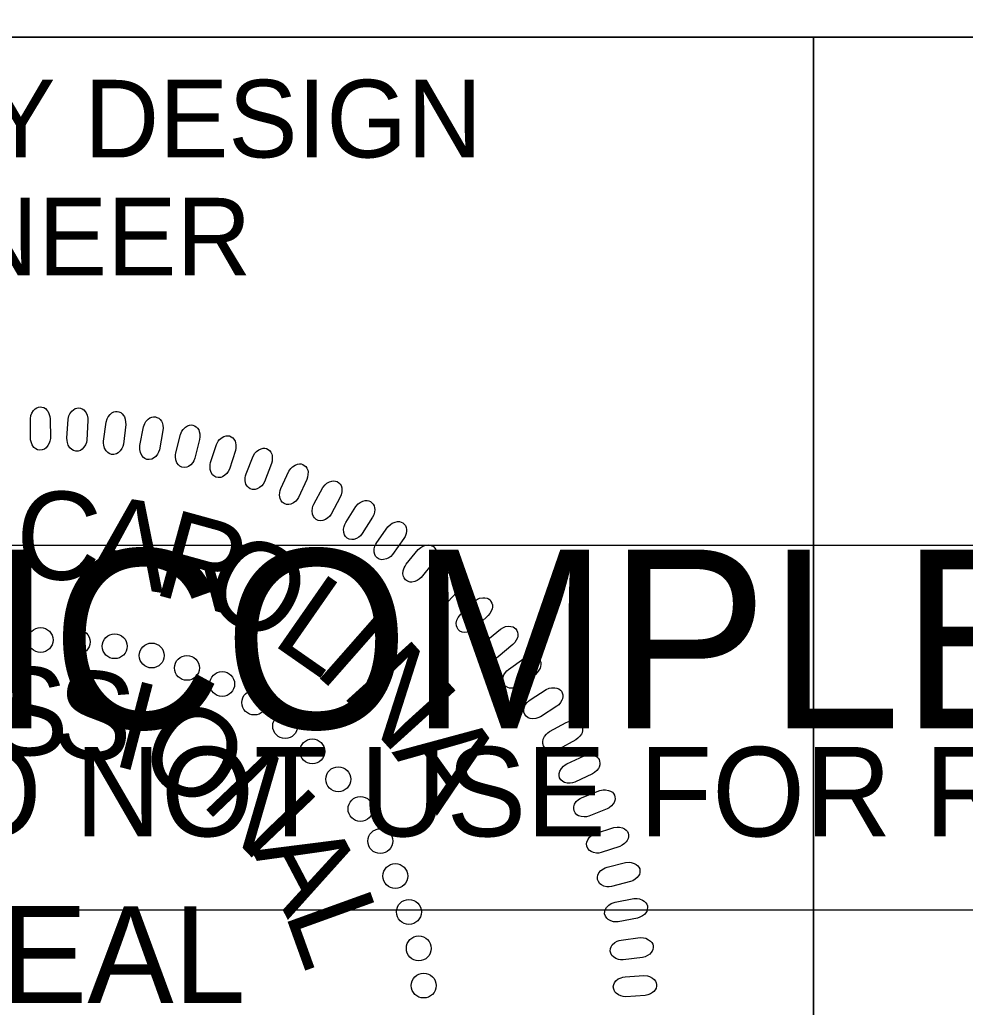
# Model space of a CAD drawing. Extents: x 505602 to 507286, y 483109 to 484209.
# Drawn here: x 507117.9 to 507178.9, y 484096.2 to 484159.8 of the extents above; entities that cross this region are included whole.
import ezdxf

# ---------------------------------------------------------------- set-up
doc = ezdxf.new("R2010")
doc.units = 0
for name, color, linetype in [('Sheet PE Seal Cell', 7, 'Continuous'), ('Sheet Profile CELL', 7, 'Continuous'), ('Sheet Sticker Incomplete CELL', 7, 'Continuous')]:
    doc.layers.add(name, color=color, linetype=linetype)

msp = doc.modelspace()

# ---------------------------------------------------------------- linework, layer by layer
at = {"layer": 'Sheet PE Seal Cell'}
for points in [[(507118.615, 484132.849), (507118.615, 484134.076), (507118.653, 484134.295), (507118.705, 484134.435), (507118.817, 484134.605), (507118.915, 484134.714), (507119.027, 484134.794), (507119.131, 484134.834), (507119.244, 484134.854), (507119.355, 484134.834), (507119.475, 484134.804), (507119.58, 484134.744), (507119.684, 484134.644), (507119.744, 484134.564), (507119.811, 484134.415), (507119.871, 484134.235), (507119.894, 484134.075), (507119.901, 484132.819), (507119.878, 484132.649), (507119.833, 484132.51), (507119.744, 484132.351), (507119.631, 484132.21), (507119.534, 484132.131), (507119.377, 484132.071), (507119.228, 484132.052), (507119.078, 484132.091), (507118.974, 484132.141), (507118.846, 484132.241), (507118.727, 484132.411), (507118.66, 484132.59), (507118.63, 484132.72)], [(507120.974, 484132.823), (507121.051, 484134.047), (507121.102, 484134.264), (507121.163, 484134.4), (507121.286, 484134.562), (507121.39, 484134.665), (507121.507, 484134.738), (507121.614, 484134.771), (507121.727, 484134.784), (507121.838, 484134.756), (507121.955, 484134.719), (507122.056, 484134.653), (507122.154, 484134.547), (507122.209, 484134.464), (507122.267, 484134.31), (507122.315, 484134.127), (507122.327, 484133.967), (507122.255, 484132.712), (507122.222, 484132.544), (507122.169, 484132.408), (507122.069, 484132.254), (507121.948, 484132.122), (507121.846, 484132.048), (507121.686, 484131.998), (507121.535, 484131.988), (507121.389, 484132.037), (507121.287, 484132.094), (507121.167, 484132.201), (507121.059, 484132.378), (507121.002, 484132.561), (507120.981, 484132.693)], [(507123.336, 484132.648), (507123.491, 484133.865), (507123.555, 484134.078), (507123.625, 484134.209), (507123.757, 484134.364), (507123.868, 484134.461), (507123.989, 484134.525), (507124.097, 484134.552), (507124.211, 484134.557), (507124.32, 484134.523), (507124.434, 484134.479), (507124.531, 484134.406), (507124.622, 484134.294), (507124.672, 484134.208), (507124.72, 484134.051), (507124.756, 484133.865), (507124.759, 484133.704), (507124.608, 484132.456), (507124.564, 484132.291), (507124.503, 484132.158), (507124.394, 484132.011), (507124.265, 484131.887), (507124.159, 484131.82), (507123.995, 484131.78), (507123.844, 484131.779), (507123.701, 484131.837), (507123.603, 484131.9), (507123.489, 484132.015), (507123.392, 484132.198), (507123.348, 484132.385), (507123.335, 484132.517)], [(507125.676, 484132.361), (507125.906, 484133.566), (507125.984, 484133.774), (507126.062, 484133.902), (507126.204, 484134.047), (507126.319, 484134.137), (507126.444, 484134.194), (507126.555, 484134.214), (507126.669, 484134.213), (507126.775, 484134.172), (507126.887, 484134.12), (507126.979, 484134.041), (507127.063, 484133.923), (507127.106, 484133.834), (507127.144, 484133.675), (507127.17, 484133.487), (507127.162, 484133.326), (507126.933, 484132.09), (507126.879, 484131.928), (507126.809, 484131.799), (507126.691, 484131.659), (507126.554, 484131.543), (507126.444, 484131.483), (507126.279, 484131.454), (507126.128, 484131.463), (507125.989, 484131.53), (507125.896, 484131.598), (507125.789, 484131.72), (507125.704, 484131.909), (507125.671, 484132.098), (507125.666, 484132.231)], [(507127.981, 484131.887), (507128.286, 484133.075), (507128.377, 484133.278), (507128.463, 484133.401), (507128.614, 484133.538), (507128.735, 484133.619), (507128.863, 484133.669), (507128.975, 484133.681), (507129.089, 484133.673), (507129.192, 484133.626), (507129.3, 484133.567), (507129.387, 484133.483), (507129.463, 484133.36), (507129.501, 484133.268), (507129.529, 484133.106), (507129.543, 484132.917), (507129.525, 484132.757), (507129.219, 484131.538), (507129.154, 484131.38), (507129.076, 484131.256), (507128.95, 484131.124), (507128.806, 484131.016), (507128.693, 484130.963), (507128.526, 484130.944), (507128.376, 484130.962), (507128.241, 484131.038), (507128.152, 484131.112), (507128.054, 484131.241), (507127.98, 484131.435), (507127.96, 484131.625), (507127.963, 484131.758)], [(507130.231, 484131.265), (507130.61, 484132.432), (507130.714, 484132.629), (507130.807, 484132.745), (507130.966, 484132.872), (507131.092, 484132.946), (507131.223, 484132.988), (507131.335, 484132.993), (507131.448, 484132.978), (507131.549, 484132.924), (507131.653, 484132.858), (507131.735, 484132.769), (507131.803, 484132.642), (507131.835, 484132.547), (507131.853, 484132.384), (507131.854, 484132.195), (507131.826, 484132.036), (507131.444, 484130.839), (507131.371, 484130.685), (507131.285, 484130.566), (507131.15, 484130.442), (507131, 484130.344), (507130.883, 484130.298), (507130.715, 484130.29), (507130.567, 484130.317), (507130.437, 484130.401), (507130.353, 484130.481), (507130.263, 484130.615), (507130.202, 484130.813), (507130.193, 484131.005), (507130.205, 484131.138)], [(507132.514, 484130.53), (507132.966, 484131.671), (507133.082, 484131.861), (507133.182, 484131.972), (507133.349, 484132.088), (507133.48, 484132.154), (507133.613, 484132.187), (507133.725, 484132.185), (507133.837, 484132.163), (507133.933, 484132.103), (507134.034, 484132.031), (507134.109, 484131.937), (507134.17, 484131.805), (507134.196, 484131.709), (507134.203, 484131.546), (507134.193, 484131.357), (507134.155, 484131.2), (507133.699, 484130.029), (507133.615, 484129.88), (507133.522, 484129.766), (507133.38, 484129.651), (507133.224, 484129.562), (507133.105, 484129.524), (507132.936, 484129.527), (507132.79, 484129.563), (507132.666, 484129.655), (507132.587, 484129.74), (507132.505, 484129.88), (507132.457, 484130.081), (507132.46, 484130.273), (507132.481, 484130.405)], [(507134.756, 484129.596), (507135.278, 484130.706), (507135.405, 484130.889), (507135.512, 484130.993), (507135.686, 484131.098), (507135.821, 484131.156), (507135.956, 484131.18), (507136.068, 484131.172), (507136.178, 484131.142), (507136.27, 484131.076), (507136.366, 484130.999), (507136.435, 484130.9), (507136.487, 484130.765), (507136.508, 484130.667), (507136.505, 484130.503), (507136.482, 484130.316), (507136.435, 484130.161), (507135.906, 484129.021), (507135.814, 484128.878), (507135.713, 484128.77), (507135.564, 484128.664), (507135.403, 484128.586), (507135.281, 484128.555), (507135.114, 484128.567), (507134.97, 484128.614), (507134.852, 484128.713), (507134.779, 484128.803), (507134.706, 484128.947), (507134.67, 484129.151), (507134.686, 484129.343), (507134.714, 484129.472)], [(507136.88, 484128.581), (507137.471, 484129.656), (507137.609, 484129.83), (507137.722, 484129.927), (507137.902, 484130.021), (507138.04, 484130.071), (507138.177, 484130.087), (507138.288, 484130.071), (507138.396, 484130.035), (507138.485, 484129.963), (507138.575, 484129.879), (507138.638, 484129.777), (507138.682, 484129.639), (507138.695, 484129.54), (507138.683, 484129.377), (507138.648, 484129.19), (507138.591, 484129.04), (507137.992, 484127.935), (507137.89, 484127.798), (507137.784, 484127.697), (507137.629, 484127.6), (507137.462, 484127.532), (507137.339, 484127.509), (507137.173, 484127.532), (507137.032, 484127.586), (507136.92, 484127.693), (507136.852, 484127.788), (507136.789, 484127.937), (507136.766, 484128.143), (507136.794, 484128.332), (507136.83, 484128.461)], [(507138.938, 484127.396), (507139.595, 484128.432), (507139.744, 484128.597), (507139.863, 484128.686), (507140.049, 484128.77), (507140.19, 484128.811), (507140.327, 484128.818), (507140.437, 484128.795), (507140.543, 484128.751), (507140.626, 484128.675), (507140.711, 484128.585), (507140.768, 484128.479), (507140.802, 484128.338), (507140.81, 484128.239), (507140.787, 484128.076), (507140.741, 484127.893), (507140.674, 484127.746), (507140.007, 484126.682), (507139.897, 484126.551), (507139.784, 484126.457), (507139.623, 484126.37), (507139.454, 484126.312), (507139.329, 484126.297), (507139.164, 484126.33), (507139.027, 484126.394), (507138.923, 484126.508), (507138.861, 484126.606), (507138.807, 484126.758), (507138.797, 484126.965), (507138.837, 484127.153), (507138.881, 484127.279)], [(507140.938, 484126.123), (507141.659, 484127.115), (507141.818, 484127.271), (507141.943, 484127.353), (507142.133, 484127.424), (507142.276, 484127.456), (507142.413, 484127.455), (507142.522, 484127.425), (507142.625, 484127.375), (507142.703, 484127.293), (507142.782, 484127.199), (507142.832, 484127.089), (507142.858, 484126.946), (507142.86, 484126.847), (507142.826, 484126.686), (507142.769, 484126.506), (507142.693, 484126.363), (507141.96, 484125.343), (507141.842, 484125.219), (507141.723, 484125.132), (507141.558, 484125.056), (507141.384, 484125.009), (507141.259, 484125.002), (507141.097, 484125.046), (507140.964, 484125.118), (507140.866, 484125.237), (507140.811, 484125.34), (507140.767, 484125.495), (507140.77, 484125.702), (507140.821, 484125.887), (507140.873, 484126.01)], [(507142.832, 484124.707), (507143.614, 484125.652), (507143.783, 484125.797), (507143.912, 484125.871), (507144.107, 484125.931), (507144.251, 484125.953), (507144.389, 484125.943), (507144.495, 484125.907), (507144.594, 484125.85), (507144.668, 484125.764), (507144.741, 484125.664), (507144.783, 484125.552), (507144.8, 484125.408), (507144.796, 484125.308), (507144.751, 484125.15), (507144.683, 484124.974), (507144.599, 484124.837), (507143.804, 484123.864), (507143.678, 484123.747), (507143.554, 484123.669), (507143.384, 484123.603), (507143.208, 484123.567), (507143.082, 484123.567), (507142.923, 484123.621), (507142.795, 484123.702), (507142.705, 484123.827), (507142.657, 484123.932), (507142.623, 484124.09), (507142.639, 484124.297), (507142.701, 484124.479), (507142.761, 484124.597)], [(507144.603, 484123.192), (507145.444, 484124.087), (507145.621, 484124.221), (507145.755, 484124.287), (507145.953, 484124.334), (507146.099, 484124.347), (507146.235, 484124.329), (507146.339, 484124.286), (507146.434, 484124.224), (507146.502, 484124.133), (507146.569, 484124.029), (507146.604, 484123.914), (507146.612, 484123.769), (507146.601, 484123.67), (507146.547, 484123.515), (507146.468, 484123.343), (507146.376, 484123.212), (507145.52, 484122.291), (507145.388, 484122.183), (507145.259, 484122.112), (507145.085, 484122.057), (507144.908, 484122.032), (507144.782, 484122.04), (507144.626, 484122.104), (507144.504, 484122.192), (507144.423, 484122.323), (507144.381, 484122.431), (507144.356, 484122.591), (507144.385, 484122.796), (507144.459, 484122.973), (507144.526, 484123.088)], [(507146.348, 484121.499), (507147.243, 484122.339), (507147.428, 484122.461), (507147.566, 484122.519), (507147.766, 484122.553), (507147.912, 484122.558), (507148.047, 484122.53), (507148.148, 484122.481), (507148.24, 484122.413), (507148.302, 484122.318), (507148.362, 484122.21), (507148.39, 484122.093), (507148.389, 484121.948), (507148.371, 484121.85), (507148.308, 484121.699), (507148.219, 484121.532), (507148.117, 484121.406), (507147.206, 484120.541), (507147.067, 484120.442), (507146.935, 484120.379), (507146.757, 484120.335), (507146.578, 484120.321), (507146.453, 484120.337), (507146.302, 484120.411), (507146.185, 484120.507), (507146.112, 484120.642), (507146.077, 484120.753), (507146.063, 484120.914), (507146.105, 484121.117), (507146.19, 484121.289), (507146.264, 484121.4)], [(507147.96, 484119.753), (507148.905, 484120.535), (507149.099, 484120.645), (507149.24, 484120.694), (507149.441, 484120.716), (507149.588, 484120.711), (507149.721, 484120.675), (507149.818, 484120.62), (507149.906, 484120.546), (507149.961, 484120.447), (507150.014, 484120.336), (507150.035, 484120.217), (507150.025, 484120.073), (507150.001, 484119.976), (507149.929, 484119.828), (507149.829, 484119.669), (507149.72, 484119.549), (507148.756, 484118.743), (507148.611, 484118.652), (507148.475, 484118.598), (507148.295, 484118.566), (507148.116, 484118.563), (507147.992, 484118.587), (507147.846, 484118.669), (507147.736, 484118.772), (507147.671, 484118.913), (507147.643, 484119.025), (507147.639, 484119.187), (507147.693, 484119.387), (507147.789, 484119.553), (507147.87, 484119.659)], [(507149.42, 484117.931), (507150.413, 484118.651), (507150.612, 484118.75), (507150.756, 484118.79), (507150.96, 484118.799), (507151.105, 484118.784), (507151.235, 484118.74), (507151.329, 484118.679), (507151.412, 484118.6), (507151.461, 484118.497), (507151.507, 484118.383), (507151.52, 484118.264), (507151.501, 484118.12), (507151.472, 484118.025), (507151.39, 484117.882), (507151.28, 484117.729), (507151.164, 484117.617), (507150.152, 484116.872), (507150.001, 484116.791), (507149.861, 484116.745), (507149.68, 484116.724), (507149.501, 484116.733), (507149.379, 484116.765), (507149.239, 484116.856), (507149.135, 484116.966), (507149.079, 484117.11), (507149.058, 484117.224), (507149.064, 484117.386), (507149.131, 484117.582), (507149.237, 484117.742), (507149.324, 484117.842)], [(507150.821, 484115.984), (507151.857, 484116.641), (507152.062, 484116.727), (507152.208, 484116.758), (507152.411, 484116.755), (507152.556, 484116.731), (507152.683, 484116.679), (507152.773, 484116.612), (507152.85, 484116.528), (507152.893, 484116.423), (507152.932, 484116.305), (507152.938, 484116.185), (507152.909, 484116.043), (507152.874, 484115.95), (507152.783, 484115.813), (507152.664, 484115.666), (507152.542, 484115.562), (507151.485, 484114.883), (507151.329, 484114.811), (507151.187, 484114.774), (507151.004, 484114.765), (507150.826, 484114.784), (507150.707, 484114.824), (507150.572, 484114.924), (507150.476, 484115.04), (507150.429, 484115.187), (507150.415, 484115.302), (507150.431, 484115.464), (507150.51, 484115.655), (507150.626, 484115.808), (507150.72, 484115.903)], [(507152.082, 484113.934), (507153.157, 484114.525), (507153.367, 484114.598), (507153.515, 484114.62), (507153.717, 484114.604), (507153.86, 484114.571), (507153.984, 484114.51), (507154.07, 484114.438), (507154.141, 484114.35), (507154.178, 484114.241), (507154.209, 484114.122), (507154.207, 484114.002), (507154.17, 484113.862), (507154.129, 484113.771), (507154.03, 484113.64), (507153.901, 484113.502), (507153.773, 484113.405), (507152.675, 484112.793), (507152.515, 484112.731), (507152.371, 484112.703), (507152.188, 484112.706), (507152.012, 484112.736), (507151.895, 484112.783), (507151.767, 484112.892), (507151.678, 484113.013), (507151.641, 484113.163), (507151.634, 484113.279), (507151.66, 484113.439), (507151.751, 484113.625), (507151.876, 484113.771), (507151.976, 484113.859)], [(507153.189, 484111.852), (507154.299, 484112.374), (507154.514, 484112.433), (507154.662, 484112.446), (507154.864, 484112.416), (507155.004, 484112.374), (507155.124, 484112.307), (507155.205, 484112.229), (507155.271, 484112.136), (507155.3, 484112.026), (507155.324, 484111.905), (507155.315, 484111.785), (507155.269, 484111.648), (507155.222, 484111.56), (507155.115, 484111.435), (507154.978, 484111.305), (507154.843, 484111.217), (507153.709, 484110.675), (507153.546, 484110.624), (507153.4, 484110.605), (507153.219, 484110.618), (507153.044, 484110.66), (507152.93, 484110.714), (507152.809, 484110.831), (507152.728, 484110.958), (507152.7, 484111.11), (507152.701, 484111.226), (507152.737, 484111.383), (507152.84, 484111.563), (507152.974, 484111.701), (507153.079, 484111.783)], [(507154.169, 484109.69), (507155.31, 484110.142), (507155.527, 484110.187), (507155.676, 484110.191), (507155.875, 484110.149), (507156.013, 484110.098), (507156.128, 484110.023), (507156.204, 484109.941), (507156.264, 484109.844), (507156.286, 484109.732), (507156.302, 484109.61), (507156.286, 484109.491), (507156.231, 484109.357), (507156.179, 484109.272), (507156.065, 484109.154), (507155.92, 484109.032), (507155.78, 484108.953), (507154.614, 484108.484), (507154.448, 484108.442), (507154.301, 484108.433), (507154.12, 484108.457), (507153.949, 484108.51), (507153.839, 484108.571), (507153.725, 484108.695), (507153.652, 484108.827), (507153.634, 484108.981), (507153.642, 484109.096), (507153.688, 484109.252), (507153.802, 484109.425), (507153.944, 484109.554), (507154.054, 484109.629)], [(507155.042, 484107.376), (507156.21, 484107.755), (507156.43, 484107.787), (507156.579, 484107.781), (507156.775, 484107.726), (507156.909, 484107.668), (507157.02, 484107.586), (507157.09, 484107.499), (507157.143, 484107.398), (507157.159, 484107.285), (507157.168, 484107.162), (507157.143, 484107.045), (507157.08, 484106.914), (507157.023, 484106.832), (507156.901, 484106.721), (507156.749, 484106.61), (507156.604, 484106.539), (507155.411, 484106.144), (507155.243, 484106.113), (507155.097, 484106.113), (507154.918, 484106.149), (507154.75, 484106.212), (507154.644, 484106.28), (507154.538, 484106.411), (507154.473, 484106.547), (507154.465, 484106.702), (507154.48, 484106.816), (507154.536, 484106.968), (507154.66, 484107.134), (507154.81, 484107.254), (507154.924, 484107.322)], [(507155.788, 484105.203), (507156.976, 484105.507), (507157.197, 484105.526), (507157.346, 484105.51), (507157.538, 484105.444), (507157.669, 484105.377), (507157.773, 484105.288), (507157.838, 484105.197), (507157.885, 484105.093), (507157.894, 484104.979), (507157.894, 484104.856), (507157.863, 484104.74), (507157.792, 484104.614), (507157.73, 484104.536), (507157.601, 484104.434), (507157.442, 484104.331), (507157.293, 484104.27), (507156.078, 484103.95), (507155.908, 484103.93), (507155.762, 484103.939), (507155.585, 484103.986), (507155.422, 484104.06), (507155.32, 484104.134), (507155.224, 484104.271), (507155.167, 484104.411), (507155.169, 484104.566), (507155.191, 484104.679), (507155.256, 484104.827), (507155.39, 484104.985), (507155.548, 484105.095), (507155.666, 484105.156)], [(507156.297, 484102.949), (507157.502, 484103.178), (507157.725, 484103.182), (507157.872, 484103.158), (507158.059, 484103.079), (507158.185, 484103.004), (507158.285, 484102.909), (507158.343, 484102.814), (507158.384, 484102.707), (507158.385, 484102.594), (507158.378, 484102.47), (507158.339, 484102.356), (507158.261, 484102.235), (507158.194, 484102.161), (507158.059, 484102.067), (507157.894, 484101.975), (507157.742, 484101.923), (507156.508, 484101.68), (507156.337, 484101.671), (507156.192, 484101.689), (507156.019, 484101.747), (507155.861, 484101.831), (507155.764, 484101.911), (507155.675, 484102.055), (507155.628, 484102.198), (507155.639, 484102.352), (507155.669, 484102.464), (507155.743, 484102.608), (507155.887, 484102.756), (507156.052, 484102.857), (507156.173, 484102.91)], [(507156.695, 484100.51), (507157.913, 484100.662), (507158.135, 484100.653), (507158.28, 484100.619), (507158.462, 484100.529), (507158.584, 484100.446), (507158.677, 484100.345), (507158.729, 484100.246), (507158.763, 484100.138), (507158.757, 484100.024), (507158.742, 484099.901), (507158.696, 484099.789), (507158.61, 484099.674), (507158.539, 484099.605), (507158.398, 484099.519), (507158.228, 484099.437), (507158.072, 484099.394), (507156.826, 484099.23), (507156.655, 484099.232), (507156.511, 484099.259), (507156.342, 484099.328), (507156.189, 484099.421), (507156.098, 484099.508), (507156.018, 484099.656), (507155.981, 484099.802), (507156.002, 484099.955), (507156.038, 484100.065), (507156.121, 484100.204), (507156.274, 484100.344), (507156.444, 484100.433), (507156.569, 484100.478)], [(507156.939, 484098.145), (507158.163, 484098.221), (507158.384, 484098.197), (507158.527, 484098.155), (507158.704, 484098.053), (507158.819, 484097.963), (507158.905, 484097.856), (507158.951, 484097.754), (507158.979, 484097.643), (507158.966, 484097.53), (507158.944, 484097.409), (507158.89, 484097.301), (507158.797, 484097.19), (507158.721, 484097.126), (507158.576, 484097.049), (507158.401, 484096.978), (507158.243, 484096.946), (507156.989, 484096.86), (507156.819, 484096.872), (507156.676, 484096.908), (507156.512, 484096.987), (507156.366, 484097.09), (507156.28, 484097.182), (507156.21, 484097.335), (507156.181, 484097.484), (507156.211, 484097.635), (507156.255, 484097.743), (507156.346, 484097.876), (507156.508, 484098.005), (507156.683, 484098.084), (507156.81, 484098.122)]]:
    msp.add_lwpolyline(points, close=True, dxfattribs=at)
for centre in [(507119.272, 484119.832), (507121.661, 484119.712), (507124.049, 484119.433), (507126.438, 484118.834), (507128.707, 484118.037), (507130.976, 484117), (507133.046, 484115.804), (507135.036, 484114.29), (507136.787, 484112.656), (507138.459, 484110.863), (507139.891, 484108.95), (507141.165, 484106.878), (507142.137, 484104.629), (507143.012, 484102.318), (507143.648, 484099.968), (507143.966, 484097.577)]:
    msp.add_circle(centre, 0.801, dxfattribs=at)
at = {"layer": 'Sheet Profile CELL'}
msp.add_line((507169.08, 484158.662), (507169.08, 484046.212), dxfattribs=at)
for points in [[(507069.03, 484183.712), (507269.08, 484183.712), (507269.08, 484158.662), (507069.03, 484158.662)], [(507069.03, 484158.662), (507169.08, 484158.662), (507169.08, 484046.162), (507069.03, 484046.162)], [(507169.08, 484158.662), (507269.08, 484158.662), (507269.08, 484046.162), (507169.08, 484046.162)]]:
    msp.add_lwpolyline(points, close=True, dxfattribs=at)
at = {"layer": 'Sheet Sticker Incomplete CELL'}
msp.add_lwpolyline([(507095.58, 484102.437), (507095.58, 484125.937), (507242.58, 484125.937), (507242.58, 484102.437)], close=True, dxfattribs=at)

# ---------------------------------------------------------------- texts
at = {"layer": 'Sheet PE Seal Cell'}
for s, height, rotation, p in [('C', 5.669, 357.58768, (507117.59, 484123.844)), ('A', 5.669, 351.09832, (507122.165, 484123.635)), ('R', 5.669, 344.60896, (507126.371, 484122.841)), ('O', 5.669, 331.63025, (507129.326, 484122.187)), ('L', 5.669, 325.14089, (507134.059, 484119.656)), ('I', 5.669, 318.65154, (507136.752, 484117.803)), ('N', 5.669, 312.16218, (507138.557, 484116.383)), ('S', 5.669, 1.28903, (507116.048, 484112.351)), ('S', 5.669, 353.34923, (507119.909, 484112.452)), ('I', 5.669, 345.40944, (507123.709, 484111.821)), ('O', 5.669, 329.52984, (507125.213, 484111.649)), ('A', 5.669, 305.67282, (507141.877, 484112.603)), ('N', 5.669, 313.65025, (507129.525, 484109.344)), ('A', 5.669, 297.77065, (507132.862, 484106.264)), ('L', 5.669, 289.83086, (507134.985, 484102.269)), ('SEAL', 6.2363, 359.98136, (507111.164, 484096.457))]:
    msp.add_text(s, height=height, rotation=rotation, dxfattribs=at).set_placement(p)
at = {"layer": 'Sheet Profile CELL'}
for s, p in [('ROADWAY DESIGN', (507085.68, 484150.912)), ('ENGINEER', (507097.93, 484143.312))]:
    msp.add_text(s, height=5.0001, dxfattribs=at).set_placement(p)
at = {"layer": 'Sheet Sticker Incomplete CELL'}
for s, height, p in [('INCOMPLETE PLANS', 11.52, (507104.53, 484114.137)), ('DO NOT USE FOR R/W ACQUISITION', 5.76, (507107.78, 484107.187))]:
    msp.add_text(s, height=height, dxfattribs=at).set_placement(p)

doc.saveas('drawing.dxf')
